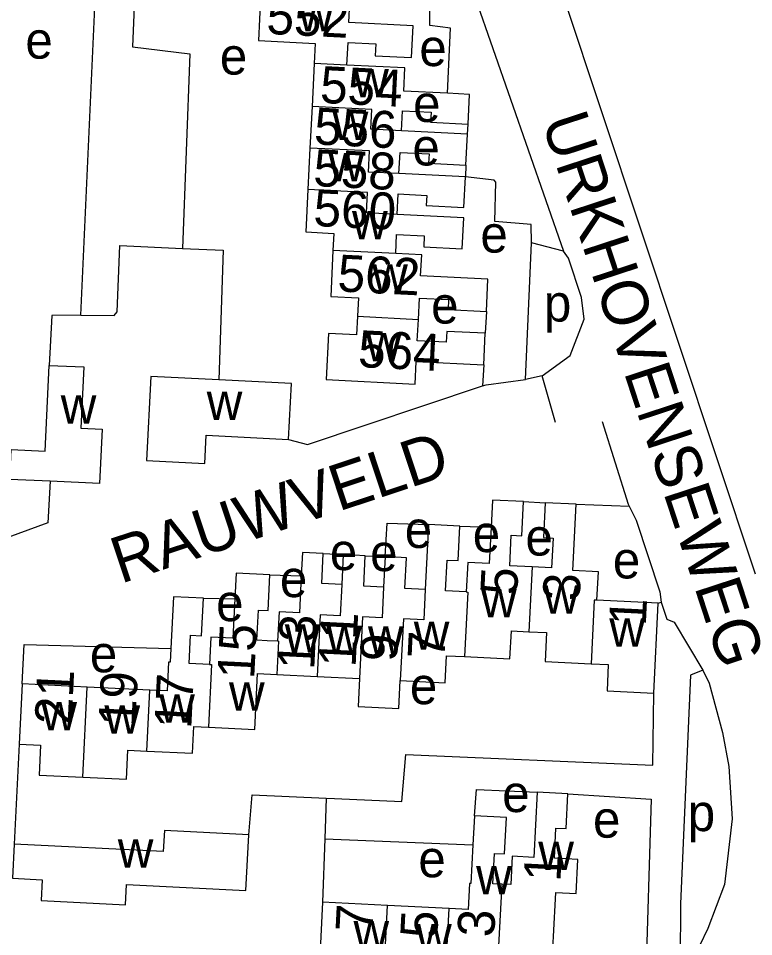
# Model space of a CAD drawing. Extents: x 163026 to 166241, y 382475 to 384501.
# Drawn here: x 164796.9 to 164876.6, y 383750 to 383849.6 of the extents above; entities that cross this region are included whole.
import ezdxf

# ---------------------------------------------------------------- set-up
doc = ezdxf.new("R2010")
doc.units = 0
for name, color, linetype in [('BLT_Basislijn', 7, 'Continuous'), ('BLT_Bebouwing', 7, 'Continuous'), ('BLT_Centroide', 7, 'Continuous'), ('BLT_Huisnummer', 7, 'Continuous'), ('BLT_Huisnummer_ tussenligend', 7, 'Continuous'), ('BLT_Onderverdeling_panden', 7, 'Continuous'), ('BLT_Straatnaam', 7, 'Continuous')]:
    doc.layers.add(name, color=color, linetype=linetype)

msp = doc.modelspace()

# ---------------------------------------------------------------- linework, layer by layer
at = {"layer": 'BLT_Basislijn'}
for p, q in [((164835.163, 383884.124), (164855.946, 383824.313)), ((164876.787, 383789.304), (164855.181, 383854.332)), ((164845.531, 383837.026), (164845.606, 383838.109)), ((164845.364, 383833.661), (164845.32, 383832.391)), ((164851.829, 383810.4), (164852.498, 383825.237)), ((164855.946, 383824.313), (164852.498, 383825.237)), ((164847.591, 383817.793), (164847.476, 383815.422)), ((164847.306, 383812.013), (164847.188, 383809.707)), ((164853.645, 383810.821), (164851.829, 383810.4)), ((164855.073, 383805.735), (164853.645, 383810.821)), ((164851.625, 383797.164), (164853.961, 383797.047)), ((164857.321, 383796.892), (164863.089, 383796.662)), ((164844.708, 383794.508), (164848.103, 383794.411)), ((164829.905, 383791.54), (164832.078, 383791.42)), ((164834.472, 383791.302), (164836.617, 383791.199)), ((164824.133, 383789.236), (164827.527, 383789.114)), ((164816.917, 383786.684), (164820.322, 383786.634)), ((164866.236, 383786.143), (164866.53, 383786.244)), ((164796.935, 383770.852), (164796.408, 383760.009)), ((164830.234, 383764.993), (164830.08, 383760.574)), ((164830.08, 383760.574), (164829.842, 383753.719)), ((164830.08, 383760.574), (164846.14, 383759.957))]:
    msp.add_line(p, q, dxfattribs=at)
for points in [[(164821.16, 383872.421), (164810.3, 383872.591), (164809.229, 383846.493), (164815.443, 383845.747), (164814.64, 383824.632)], [(164803.64, 383817.373), (164805.819, 383865.932), (164805.596, 383866.187), (164797.343, 383866.526)], [(164843.38, 383841.456), (164843.696, 383848.532), (164841.447, 383848.806), (164841.474, 383855.332), (164837.218, 383855.532)], [(164852.498, 383825.237), (164852.441, 383827.232), (164848.496, 383827.545), (164848.604, 383831.802), (164848.445, 383832.044), (164845.32, 383832.391)], [(164803.64, 383817.373), (164807.241, 383817.353), (164807.559, 383817.736), (164807.862, 383824.944), (164814.64, 383824.632)], [(164814.64, 383824.632), (164819.076, 383824.428), (164818.592, 383810.374)], [(164853.645, 383810.821), (164856.666, 383813), (164858.209, 383816.952), (164857.903, 383819.31), (164856.481, 383823.587), (164855.946, 383824.313)], [(164803.64, 383817.373), (164800.479, 383817.345), (164800.205, 383811.943)], [(164847.188, 383809.707), (164847.584, 383809.839), (164851.829, 383810.4)], [(164826.153, 383803.92), (164828.215, 383803.37), (164847.188, 383809.707)], [(164860.14, 383805.862), (164862.976, 383796.889), (164863.089, 383796.662)], [(164800.309, 383799.373), (164800.07, 383794.855), (164789.586, 383791.044), (164788.949, 383791.044), (164787.579, 383793.262), (164774.398, 383794.052)], [(164863.089, 383796.662), (164863.836, 383795.161), (164866.392, 383787.398), (164866.53, 383786.244)], [(164836.617, 383791.199), (164836.842, 383794.832), (164841.304, 383794.676)], [(164866.53, 383786.244), (164867.157, 383784.429), (164867.96, 383784.084), (164871.045, 383778.884)], [(164797.258, 383777.407), (164797.475, 383781.671), (164813.4, 383781.225)], [(164871.045, 383778.884), (164869.732, 383778.361), (164868.623, 383753.556), (164868.616, 383747.412)], [(164871.045, 383778.884), (164871.765, 383777.462), (164873.199, 383772.128), (164873.862, 383768.425), (164874.244, 383762.778), (164873.397, 383755.64), (164871.606, 383750.866), (164869.796, 383747.099), (164869.368, 383747.099), (164868.616, 383747.412)], [(164830.234, 383764.993), (164831.141, 383764.951), (164838.414, 383764.624), (164838.865, 383769.744), (164865.626, 383768.584), (164865.756, 383776.39)], [(164821.831, 383761.04), (164822.202, 383765.369), (164830.234, 383764.993)], [(164846.299, 383763.084), (164846.52, 383765.948), (164853.085, 383765.654)], [(164856.421, 383765.484), (164865.474, 383764.9), (164864.837, 383744.563)]]:
    msp.add_lwpolyline(points, dxfattribs=at)
at = {"layer": 'BLT_Bebouwing'}
for p, q in [((164828.922, 383844.685), (164828.691, 383840.031)), ((164845.364, 383833.661), (164845.531, 383837.026)), ((164828.467, 383835.515), (164828.244, 383831.022)), ((164847.306, 383812.013), (164847.476, 383815.422)), ((164857.321, 383796.892), (164853.961, 383797.047)), ((164844.708, 383794.508), (164841.304, 383794.676)), ((164834.472, 383791.302), (164832.078, 383791.42)), ((164824.877, 383778.422), (164829.246, 383778.207)), ((164829.246, 383778.207), (164833.828, 383777.982)), ((164797.258, 383777.407), (164796.935, 383770.852)), ((164804.325, 383777.059), (164797.258, 383777.407)), ((164811.102, 383776.726), (164804.325, 383777.059)), ((164856.421, 383765.484), (164853.085, 383765.654)), ((164846.299, 383763.084), (164846.14, 383759.957)), ((164829.842, 383753.719), (164829.652, 383750)), ((164836.875, 383753.36), (164829.842, 383753.719)), ((164843.558, 383753.02), (164836.875, 383753.36))]:
    msp.add_line(p, q, dxfattribs=at)
for points in [[(164823.123, 383851.855), (164822.891, 383847.176), (164829.032, 383846.871), (164828.922, 383844.685)], [(164832.475, 383844.51), (164832.596, 383846.951), (164835.611, 383846.802), (164835.547, 383845.518), (164839.484, 383845.322), (164839.655, 383848.771), (164832.685, 383849.117), (164832.798, 383851.384), (164829.92, 383851.525)], [(164843.38, 383841.456), (164838.64, 383841.691), (164838.765, 383844.199), (164832.475, 383844.51)], [(164845.606, 383838.109), (164845.766, 383841.338), (164843.38, 383841.456)], [(164828.691, 383840.031), (164828.467, 383835.515)], [(164838.38, 383837.38), (164838.487, 383839.547), (164841.609, 383839.392), (164841.555, 383838.31), (164845.606, 383838.109)], [(164845.531, 383837.026), (164838.38, 383837.38)], [(164838.12, 383832.75), (164838.232, 383835.037), (164841.38, 383834.88), (164841.33, 383833.861), (164845.364, 383833.661)], [(164845.32, 383832.391), (164838.12, 383832.75)], [(164837.915, 383828.315), (164838.024, 383830.536), (164841.135, 383830.381), (164841.08, 383829.277), (164845.155, 383829.074), (164845.32, 383832.391)], [(164828.244, 383831.022), (164828.016, 383826.413), (164831.054, 383826.262), (164830.963, 383824.402)], [(164837.761, 383824.064), (164837.863, 383826.127), (164840.856, 383825.979), (164840.798, 383824.798), (164844.969, 383824.591), (164845.136, 383827.955), (164837.915, 383828.315)], [(164830.963, 383824.402), (164830.715, 383819.429), (164833.714, 383819.28), (164833.613, 383817.263)], [(164847.591, 383817.793), (164847.764, 383821.285), (164840.47, 383821.647), (164840.583, 383823.924), (164837.761, 383824.064)], [(164840.221, 383816.934), (164840.335, 383819.232), (164843.495, 383819.075), (164843.442, 383817.999), (164847.591, 383817.793)], [(164833.613, 383817.263), (164833.513, 383815.246), (164830.481, 383815.397), (164830.233, 383810.395), (164839.866, 383809.917), (164839.988, 383812.376), (164847.306, 383812.013)], [(164847.476, 383815.422), (164843.306, 383815.629), (164843.249, 383814.467), (164840.106, 383814.623), (164840.221, 383816.934)], [(164800.309, 383799.373), (164795.925, 383799.578), (164796.076, 383802.825), (164799.772, 383802.653), (164800.205, 383811.943)], [(164800.205, 383811.943), (164803.94, 383811.768), (164803.632, 383805.15), (164805.947, 383805.042), (164805.671, 383799.123), (164800.309, 383799.373)], [(164818.592, 383810.374), (164811.208, 383810.74), (164810.756, 383801.627), (164817.061, 383801.314), (164817.212, 383804.364), (164826.153, 383803.92)], [(164826.153, 383803.92), (164826.454, 383809.983), (164818.592, 383810.374)], [(164851.625, 383797.164), (164848.246, 383797.33), (164848.103, 383794.411)], [(164852.559, 383790.088), (164850.134, 383790.208), (164850.298, 383793.524), (164851.443, 383793.467), (164851.625, 383797.164)], [(164853.961, 383797.047), (164853.787, 383793.259), (164854.832, 383793.207), (164854.673, 383789.984), (164852.559, 383790.088)], [(164859.581, 383786.471), (164859.733, 383789.559), (164856.975, 383789.695), (164857.321, 383796.892)], [(164841.304, 383794.676), (164840.96, 383787.645)], [(164845.412, 383787.369), (164843.165, 383787.479), (164843.329, 383790.829), (164844.524, 383790.771), (164844.708, 383794.508)], [(164848.103, 383794.411), (164847.908, 383790.449), (164845.569, 383790.564), (164845.412, 383787.369)], [(164829.905, 383791.54), (164827.652, 383791.65), (164827.527, 383789.114)], [(164831.92, 383788.195), (164829.745, 383788.303), (164829.905, 383791.54)], [(164832.078, 383791.42), (164831.92, 383788.195)], [(164836.455, 383787.875), (164834.308, 383787.979), (164834.472, 383791.302)], [(164836.617, 383791.199), (164836.455, 383787.875)], [(164840.96, 383787.645), (164838.761, 383787.756), (164838.925, 383791.086), (164836.617, 383791.199)], [(164824.133, 383789.236), (164820.459, 383789.417), (164820.322, 383786.634)], [(164823.839, 383782.074), (164822.718, 383782.129), (164822.879, 383785.4), (164823.941, 383785.348), (164824.133, 383789.236)], [(164827.527, 383789.114), (164827.33, 383785.119), (164825.119, 383785.228), (164824.961, 383782.019)], [(164845.412, 383787.369), (164845.574, 383787.362)], [(164816.917, 383786.684), (164813.677, 383786.844), (164813.4, 383781.225)], [(164817.577, 383779.51), (164815.383, 383779.618), (164815.533, 383782.664), (164816.717, 383782.606), (164816.917, 383786.684)], [(164820.322, 383786.634), (164820.111, 383782.352), (164817.723, 383782.469), (164817.577, 383779.51)], [(164866.236, 383786.143), (164859.581, 383786.471)], [(164865.756, 383776.39), (164866.236, 383786.143)], [(164845.223, 383780.353), (164850.155, 383780.109), (164850.304, 383783.146), (164852.212, 383783.052)], [(164852.212, 383783.052), (164854.126, 383782.958), (164853.972, 383779.831), (164858.949, 383779.586)], [(164824.961, 383782.019), (164823.839, 383782.074)], [(164825.056, 383782.015), (164824.961, 383782.019)], [(164813.4, 383781.225), (164813.327, 383779.741), (164813.138, 383779.75), (164812.984, 383776.633), (164811.102, 383776.726)], [(164838.265, 383777.764), (164843.114, 383777.524), (164843.258, 383780.449), (164845.223, 383780.353)], [(164858.949, 383779.586), (164860.813, 383779.494), (164860.673, 383776.64), (164865.756, 383776.39)], [(164817.468, 383772.696), (164822.491, 383772.449), (164822.79, 383778.525), (164824.877, 383778.422)], [(164833.828, 383777.982), (164833.679, 383774.947), (164838.116, 383774.729), (164838.265, 383777.764)], [(164810.776, 383770.115), (164815.752, 383769.87), (164815.895, 383772.774), (164817.468, 383772.696)], [(164796.935, 383770.852), (164799.27, 383770.737), (164799.111, 383767.514), (164803.843, 383767.281)], [(164803.843, 383767.281), (164808.575, 383767.048), (164808.731, 383770.216), (164810.776, 383770.115)], [(164853.085, 383765.654), (164852.724, 383758.58), (164850.386, 383758.699), (164850.229, 383755.627), (164849.262, 383755.676)], [(164854.887, 383750), (164855.131, 383754.788), (164857.318, 383754.677), (164857.505, 383758.357), (164854.966, 383758.486), (164855.133, 383761.764), (164856.228, 383761.709), (164856.421, 383765.484)], [(164849.262, 383755.676), (164848.296, 383755.725), (164848.463, 383759.014), (164849.566, 383758.958), (164849.768, 383762.907), (164846.299, 383763.084)], [(164796.408, 383760.009), (164796.226, 383756.313), (164799.453, 383756.154), (164799.342, 383753.894), (164808.456, 383753.446), (164808.564, 383755.628), (164821.533, 383754.99), (164821.831, 383761.04)], [(164821.831, 383761.04), (164812.682, 383761.49), (164812.57, 383759.213), (164796.408, 383760.009)], [(164846.14, 383759.957), (164845.926, 383755.757), (164845.758, 383755.765), (164845.613, 383752.915), (164843.558, 383753.02)], [(164829.652, 383750), (164829.486, 383746.946), (164830.457, 383746.895)], [(164848.923, 383748.978), (164854.815, 383748.681), (164854.887, 383750)]]:
    msp.add_lwpolyline(points, dxfattribs=at)
at = {"layer": 'BLT_Onderverdeling_panden'}
for p, q in [((164832.475, 383844.51), (164828.922, 383844.685)), ((164837.761, 383824.064), (164830.963, 383824.402)), ((164833.613, 383817.263), (164840.221, 383816.934)), ((164852.559, 383790.088), (164852.212, 383783.052)), ((164845.574, 383787.362), (164845.223, 383780.353)), ((164825.056, 383782.015), (164824.877, 383778.422)), ((164803.843, 383767.281), (164804.325, 383777.059)), ((164810.776, 383770.115), (164811.102, 383776.726)), ((164849.262, 383755.676), (164848.923, 383748.978)), ((164836.373, 383743.521), (164836.875, 383753.36)), ((164843.211, 383746.229), (164843.558, 383753.02))]:
    msp.add_line(p, q, dxfattribs=at)
for points in [[(164838.38, 383837.38), (164835.056, 383837.545), (164835.164, 383839.71), (164828.691, 383840.031)], [(164838.12, 383832.75), (164834.826, 383832.915), (164834.94, 383835.197), (164828.467, 383835.515)], [(164837.915, 383828.315), (164834.606, 383828.48), (164834.717, 383830.7), (164828.244, 383831.022)], [(164831.92, 383788.195), (164831.751, 383784.79), (164829.577, 383784.897), (164829.246, 383778.207)], [(164836.455, 383787.875), (164836.296, 383784.567), (164834.151, 383784.672), (164833.828, 383777.982)], [(164840.96, 383787.645), (164840.798, 383784.345), (164838.596, 383784.453), (164838.265, 383777.764)], [(164859.581, 383786.471), (164859.295, 383786.484), (164858.949, 383779.586)], [(164817.577, 383779.51), (164817.813, 383779.498), (164817.468, 383772.696)]]:
    msp.add_lwpolyline(points, dxfattribs=at)

# ---------------------------------------------------------------- texts
at = {"layer": 'BLT_Centroide'}
for s, p in [('w', (164827.199, 383848.188)), ('e', (164797.615, 383845.211)), ('e', (164840.324, 383844.404)), ('e', (164818.702, 383843.485)), ('w', (164833.16, 383841.031)), ('e', (164839.648, 383838.341)), ('w', (164830.925, 383836.375)), ('e', (164839.573, 383833.626)), ('w', (164830.474, 383831.906)), ('w', (164833.031, 383825.606)), ('e', (164846.942, 383824.177)), ('w', (164835.211, 383819.816)), ('p', (164853.83, 383816.697)), ('e', (164841.603, 383816.481)), ('w', (164834.535, 383812.371)), ('w', (164817.276, 383806.031)), ('w', (164801.449, 383805.625)), ('e', (164838.745, 383792.144)), ('e', (164846.114, 383791.693)), ('e', (164851.829, 383791.317)), ('e', (164830.624, 383789.736)), ('e', (164834.986, 383789.627)), ('e', (164861.304, 383788.836)), ('e', (164825.21, 383786.806)), ('w', (164853.784, 383785.001)), ('e', (164818.293, 383784.202)), ('w', (164847.017, 383784.625)), ('w', (164839.723, 383781.091)), ('w', (164860.928, 383781.422)), ('w', (164825.737, 383780.79)), ('w', (164830.248, 383780.639)), ('w', (164834.76, 383780.564)), ('e', (164804.607, 383778.652)), ('e', (164839.302, 383775.195)), ('w', (164819.691, 383774.492)), ('w', (164812.127, 383773.195)), ('w', (164799.344, 383772.344)), ('w', (164806.186, 383772)), ('e', (164849.306, 383763.496)), ('p', (164869.421, 383761.428)), ('e', (164859.151, 383760.718)), ('w', (164807.635, 383757.469)), ('w', (164853.219, 383757.203)), ('e', (164840.218, 383756.423)), ('w', (164846.484, 383754.562)), ('w', (164833.188, 383748.625)), ('w', (164839.969, 383748.266))]:
    msp.add_text(s, height=4, dxfattribs=at).set_placement(p)
at = {"layer": 'BLT_Huisnummer'}
for s, rotation, p in [('554', 357.15539, (164829.505, 383840.421)), ('558', 357.15539, (164828.778, 383831.401)), ('564', 357.15539, (164833.628, 383811.771)), ('5', 87.18243, (164850.923, 383786.974)), ('1', 87.18243, (164864.873, 383783.642)), ('13', 87.18243, (164828.927, 383778.889)), ('9', 87.18243, (164837.884, 383779.757)), ('21', 87.18243, (164802.62, 383772.914)), ('17', 87.18243, (164815.595, 383772.471)), ('1', 87.08269, (164855.615, 383755.902)), ('7', 87.08023, (164835.229, 383750.413))]:
    msp.add_text(s, height=4, rotation=rotation, dxfattribs=at).set_placement(p)
at = {"layer": 'BLT_Huisnummer_ tussenligend'}
for s, rotation, p in [('552', 357.15539, (164823.699, 383847.906)), ('556', 357.15539, (164828.855, 383835.92)), ('560', 357.15539, (164828.793, 383827.073)), ('562', 357.15539, (164831.402, 383819.974)), ('3', 87.18243, (164857.691, 383786.352)), ('11', 87.18243, (164833.412, 383779.157)), ('15', 87.18243, (164822.419, 383777.865)), ('7', 87.18243, (164843.042, 383780.027)), ('19', 87.18243, (164809.528, 383772.722)), ('5', 87.08269, (164842.243, 383749.747)), ('3', 87.08269, (164848.433, 383749.867))]:
    msp.add_text(s, height=4, rotation=rotation, dxfattribs=at).set_placement(p)
at = {"layer": 'BLT_Straatnaam'}
for s, height, rotation, p in [('URKHOVENSEWEG', 5, 288.14981, (164853.559, 383838.429)), ('RAUWVELD', 4.9999, 18.34847, (164807.945, 383788.241))]:
    msp.add_text(s, height=height, rotation=rotation, dxfattribs=at).set_placement(p)

doc.saveas('drawing.dxf')
